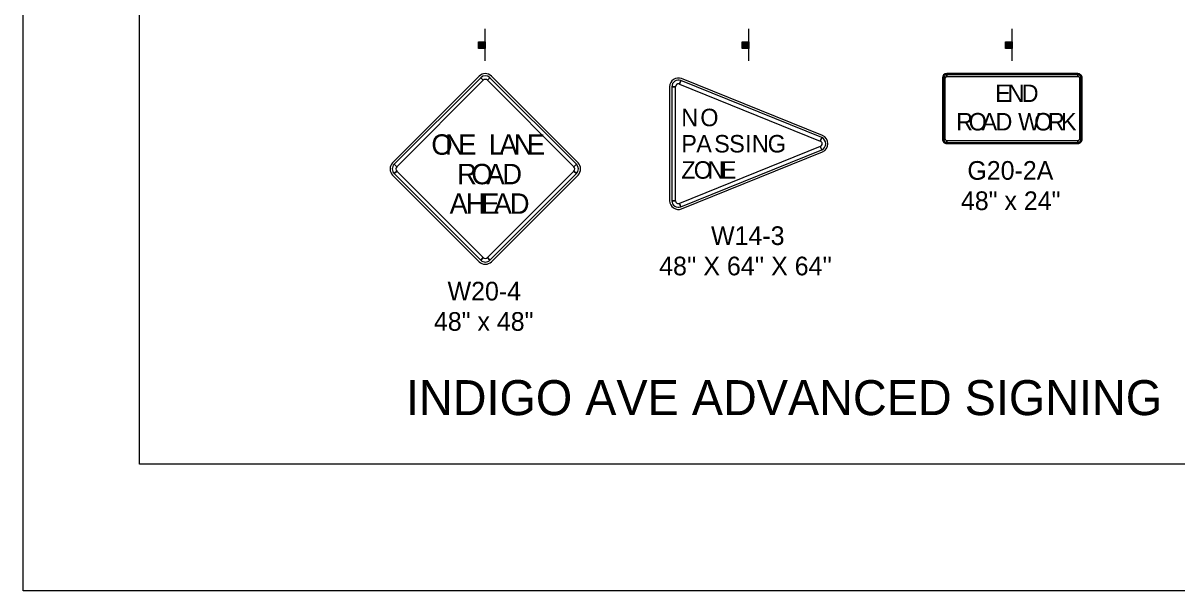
# Model space of a CAD drawing. Extents: x -2134934 to -2122394, y -2139046 to -2137036.
# Drawn here: x -2125529 to -2124540, y -2139046 to -2138559 of the extents above; entities that cross this region are included whole.
import ezdxf

# ---------------------------------------------------------------- set-up
doc = ezdxf.new("R2010")
doc.units = 0
for name, color, linetype in [('Barrier', 7, 'Continuous'), ('BridgeSuperStructureExisting', 7, 'Continuous'), ('Default', 7, 'Continuous')]:
    doc.layers.add(name, color=color, linetype=linetype)

msp = doc.modelspace()

# ---------------------------------------------------------------- linework, layer by layer
at = {"layer": 'Barrier'}
for p, q in [((-2125138.25, -2138604.6), (-2125212.49, -2138678.85)), ((-2125136.92, -2138605.93), (-2125134.71, -2138608.14)), ((-2125131.18, -2138608.14), (-2125128.97, -2138605.93)), ((-2125053.4, -2138678.85), (-2125127.64, -2138604.6)), ((-2124966.38, -2138611.33), (-2124965.21, -2138608.43)), ((-2124843.68, -2138655.57), (-2124964.51, -2138606.7)), ((-2124740.87, -2138606.15), (-2124740.87, -2138658.65)), ((-2124739.93, -2138606.15), (-2124738.37, -2138606.15)), ((-2124624.62, -2138602.4), (-2124737.12, -2138602.4)), ((-2124737.12, -2138604.9), (-2124737.12, -2138603.34)), ((-2124624.62, -2138603.34), (-2124624.62, -2138604.9)), ((-2124623.37, -2138606.15), (-2124621.81, -2138606.15)), ((-2124620.87, -2138658.65), (-2124620.87, -2138606.15)), ((-2124974.82, -2138613.65), (-2124974.82, -2138711.4)), ((-2124972.95, -2138613.65), (-2124969.82, -2138613.65)), ((-2124844.39, -2138657.31), (-2124845.56, -2138660.21)), ((-2124738.37, -2138658.65), (-2124739.93, -2138658.65)), ((-2124737.12, -2138661.47), (-2124737.12, -2138659.9)), ((-2124624.62, -2138659.9), (-2124624.62, -2138661.47)), ((-2124621.81, -2138658.65), (-2124623.37, -2138658.65)), ((-2124964.51, -2138718.35), (-2124843.68, -2138669.48)), ((-2124845.56, -2138664.84), (-2124844.39, -2138667.74)), ((-2124737.12, -2138662.4), (-2124624.62, -2138662.4)), ((-2125212.49, -2138689.45), (-2125138.25, -2138763.7)), ((-2125208.96, -2138682.38), (-2125211.17, -2138680.17)), ((-2125211.17, -2138688.13), (-2125208.96, -2138685.92)), ((-2125127.64, -2138763.7), (-2125053.4, -2138689.45)), ((-2125054.72, -2138680.17), (-2125056.93, -2138682.38)), ((-2125056.93, -2138685.92), (-2125054.72, -2138688.13)), ((-2124969.82, -2138711.4), (-2124972.95, -2138711.4)), ((-2124965.21, -2138716.61), (-2124966.38, -2138713.72)), ((-2125134.71, -2138760.16), (-2125136.92, -2138762.37)), ((-2125128.97, -2138762.37), (-2125131.18, -2138760.16))]:
    msp.add_line(p, q, dxfattribs=at)
for points in [[(-2125429.46, -2138086.59), (-2124308.22, -2138086.59), (-2124308.22, -2138937.23), (-2125429.46, -2138937.23)], [(-2125136.92, -2138605.93), (-2125211.17, -2138680.17), (-2125208.96, -2138682.38), (-2125134.71, -2138608.14), (-2125136.92, -2138605.93)], [(-2125054.72, -2138680.17), (-2125128.97, -2138605.93), (-2125131.18, -2138608.14), (-2125056.93, -2138682.38), (-2125054.72, -2138680.17)], [(-2124844.39, -2138657.31), (-2124965.21, -2138608.43), (-2124966.38, -2138611.33), (-2124845.56, -2138660.21), (-2124844.39, -2138657.31)], [(-2124739.93, -2138606.15), (-2124739.93, -2138658.65), (-2124738.37, -2138658.65), (-2124738.37, -2138606.15), (-2124739.93, -2138606.15)], [(-2124624.62, -2138603.34), (-2124737.12, -2138603.34), (-2124737.12, -2138604.9), (-2124624.62, -2138604.9), (-2124624.62, -2138603.34)], [(-2124621.81, -2138658.65), (-2124621.81, -2138606.15), (-2124623.37, -2138606.15), (-2124623.37, -2138658.65), (-2124621.81, -2138658.65)], [(-2124972.95, -2138613.65), (-2124972.95, -2138711.4), (-2124969.82, -2138711.4), (-2124969.82, -2138613.65), (-2124972.95, -2138613.65)], [(-2124737.12, -2138661.47), (-2124624.62, -2138661.47), (-2124624.62, -2138659.9), (-2124737.12, -2138659.9), (-2124737.12, -2138661.47)], [(-2124965.21, -2138716.61), (-2124844.39, -2138667.74), (-2124845.56, -2138664.84), (-2124966.38, -2138713.72), (-2124965.21, -2138716.61)], [(-2125211.17, -2138688.13), (-2125136.92, -2138762.37), (-2125134.71, -2138760.16), (-2125208.96, -2138685.92), (-2125211.17, -2138688.13)], [(-2125128.97, -2138762.37), (-2125054.72, -2138688.13), (-2125056.93, -2138685.92), (-2125131.18, -2138760.16), (-2125128.97, -2138762.37)]]:
    msp.add_lwpolyline(points, close=True, dxfattribs=at)
for centre, radius, start, end in [((-2125132.94, -2138609.9), 7.5, 44.99999, 134.99974), ((-2125132.94, -2138609.9), 5.62, 44.99999, 134.99974), ((-2125132.94, -2138609.9), 2.5, 44.99999, 134.99974), ((-2124967.32, -2138613.65), 7.5, 67.97571, 179.99985), ((-2124967.32, -2138613.65), 5.62, 67.97571, 179.99985), ((-2124737.12, -2138606.15), 3.75, 90.00021, 179.99985), ((-2124737.12, -2138606.15), 2.81, 90.00021, 179.99985), ((-2124737.12, -2138606.15), 1.25, 90.00021, 179.99985), ((-2124624.62, -2138606.15), 3.75, 0, 90.00021), ((-2124624.62, -2138606.15), 2.81, 0, 90.00021), ((-2124624.62, -2138606.15), 1.25, 0, 90.00021), ((-2124967.32, -2138613.65), 2.5, 67.97571, 179.99985), ((-2124846.5, -2138662.52), 2.5, 292.02456, 67.97541), ((-2124846.5, -2138662.52), 5.62, 292.02456, 67.97541), ((-2124846.5, -2138662.52), 7.5, 292.02456, 67.97598), ((-2124737.12, -2138658.65), 3.75, 179.99985, 270.00006), ((-2124737.12, -2138658.65), 2.81, 179.99985, 270.00006), ((-2124737.12, -2138658.65), 1.25, 179.99985, 270.00006), ((-2124624.62, -2138658.65), 3.75, 270.00006, 0.00027), ((-2124624.62, -2138658.65), 2.81, 270.00006, 0.00027), ((-2124624.62, -2138658.65), 1.25, 270.00006, 0.00027), ((-2125207.19, -2138684.15), 7.5, 134.99974, 224.99995), ((-2125058.7, -2138684.15), 7.5, 315.00016, 44.9998), ((-2125207.19, -2138684.15), 5.62, 134.99974, 224.99995), ((-2125207.19, -2138684.15), 2.5, 134.99974, 224.99995), ((-2125058.7, -2138684.15), 2.5, 315.00016, 44.9998), ((-2125058.7, -2138684.15), 5.62, 315.00016, 44.9998), ((-2124967.32, -2138711.4), 7.5, 179.99985, 292.02456), ((-2124967.32, -2138711.4), 5.62, 179.99985, 292.02456), ((-2124967.32, -2138711.4), 2.5, 179.99985, 292.02456), ((-2125132.94, -2138758.4), 7.5, 224.99995, 315.00016), ((-2125132.94, -2138758.4), 5.62, 224.99995, 315.00016), ((-2125132.94, -2138758.4), 2.5, 224.99995, 315.00016)]:
    msp.add_arc(centre, radius, start, end, dxfattribs=at)
at = {"layer": 'BridgeSuperStructureExisting'}
for p, q in [((-2125132.94, -2138591.58), (-2125132.94, -2138564.08)), ((-2124906.91, -2138591.58), (-2124906.91, -2138564.08)), ((-2124680.87, -2138591.58), (-2124680.87, -2138564.08)), ((-2125138.27, -2138580.72), (-2125138.27, -2138575.13)), ((-2125137.95, -2138575.13), (-2125137.95, -2138580.72)), ((-2125137.73, -2138580.72), (-2125137.73, -2138575.13)), ((-2125137.41, -2138575.13), (-2125137.41, -2138580.72)), ((-2125137.18, -2138580.72), (-2125137.2, -2138575.13)), ((-2125136.77, -2138575.13), (-2125136.75, -2138580.72)), ((-2125136.55, -2138580.72), (-2125136.55, -2138575.13)), ((-2125136.11, -2138575.13), (-2125136.11, -2138580.72)), ((-2125135.74, -2138580.72), (-2125135.74, -2138575.13)), ((-2125135.42, -2138575.13), (-2125135.4, -2138580.72)), ((-2125135.2, -2138580.72), (-2125135.2, -2138575.13)), ((-2125134.93, -2138575.13), (-2125134.93, -2138580.72)), ((-2125134.6, -2138580.72), (-2125134.6, -2138575.13)), ((-2125134.39, -2138575.13), (-2125134.39, -2138580.72)), ((-2125134.16, -2138580.72), (-2125134.16, -2138575.13)), ((-2125133.9, -2138575.13), (-2125133.9, -2138580.72)), ((-2125133.64, -2138580.72), (-2125133.64, -2138575.13)), ((-2125133.36, -2138575.13), (-2125133.36, -2138580.72)), ((-2124912.23, -2138580.72), (-2124912.23, -2138575.13)), ((-2124911.92, -2138575.13), (-2124911.92, -2138580.72)), ((-2124911.69, -2138580.72), (-2124911.69, -2138575.13)), ((-2124911.37, -2138575.13), (-2124911.37, -2138580.72)), ((-2124911.15, -2138580.72), (-2124911.17, -2138575.13)), ((-2124910.73, -2138575.13), (-2124910.72, -2138580.72)), ((-2124910.51, -2138580.72), (-2124910.51, -2138575.13)), ((-2124910.08, -2138575.13), (-2124910.08, -2138580.72)), ((-2124909.7, -2138580.72), (-2124909.7, -2138575.13)), ((-2124909.38, -2138575.13), (-2124909.37, -2138580.72)), ((-2124909.16, -2138580.72), (-2124909.16, -2138575.13)), ((-2124908.9, -2138575.13), (-2124908.9, -2138580.72)), ((-2124908.56, -2138580.72), (-2124908.56, -2138575.13)), ((-2124908.35, -2138575.13), (-2124908.35, -2138580.72)), ((-2124908.13, -2138580.72), (-2124908.13, -2138575.13)), ((-2124907.87, -2138575.13), (-2124907.87, -2138580.72)), ((-2124907.6, -2138580.72), (-2124907.6, -2138575.13)), ((-2124907.32, -2138575.13), (-2124907.32, -2138580.72)), ((-2124686.2, -2138580.72), (-2124686.2, -2138575.13)), ((-2124685.88, -2138575.13), (-2124685.88, -2138580.72)), ((-2124685.65, -2138580.72), (-2124685.65, -2138575.13)), ((-2124685.34, -2138575.13), (-2124685.34, -2138580.72)), ((-2124685.11, -2138580.72), (-2124685.13, -2138575.13)), ((-2124684.7, -2138575.13), (-2124684.68, -2138580.72)), ((-2124684.47, -2138580.72), (-2124684.47, -2138575.13)), ((-2124684.04, -2138575.13), (-2124684.04, -2138580.72)), ((-2124683.67, -2138580.72), (-2124683.67, -2138575.13)), ((-2124683.35, -2138575.13), (-2124683.33, -2138580.72)), ((-2124683.12, -2138580.72), (-2124683.12, -2138575.13)), ((-2124682.86, -2138575.13), (-2124682.86, -2138580.72)), ((-2124682.52, -2138580.72), (-2124682.52, -2138575.13)), ((-2124682.32, -2138575.13), (-2124682.32, -2138580.72)), ((-2124682.09, -2138580.72), (-2124682.09, -2138575.13)), ((-2124681.83, -2138575.13), (-2124681.83, -2138580.72)), ((-2124681.57, -2138580.72), (-2124681.57, -2138575.13)), ((-2124681.29, -2138575.13), (-2124681.29, -2138580.72))]:
    msp.add_line(p, q, dxfattribs=at)
for points in [[(-2125133.04, -2138575.13), (-2125133.04, -2138580.76), (-2125138.66, -2138580.76), (-2125138.66, -2138575.13)], [(-2124907, -2138575.13), (-2124907, -2138580.76), (-2124912.63, -2138580.76), (-2124912.63, -2138575.13)], [(-2124680.97, -2138575.13), (-2124680.97, -2138580.76), (-2124686.59, -2138580.76), (-2124686.59, -2138575.13)]]:
    msp.add_lwpolyline(points, close=True, dxfattribs=at)
at = {"layer": 'Default'}
msp.add_lwpolyline([(-2125529.46, -2137035.95), (-2122394.47, -2137035.95), (-2122394.47, -2139045.94), (-2125529.46, -2139045.94)], close=True, dxfattribs=at)

# ---------------------------------------------------------------- texts
at = {"layer": 'Barrier'}
for s, height, p in [('E', 15, (-2124695.54, -2138626.78)), ('N', 15, (-2124684.93, -2138626.78)), ('D', 15, (-2124672.84, -2138626.78)), ('N', 15, (-2124964.85, -2138647.52)), ('O', 15, (-2124948.51, -2138647.52)), ('R', 15, (-2124729.01, -2138651.15)), ('O', 15, (-2124718.33, -2138651.15)), ('A', 15, (-2124707.17, -2138651.15)), ('D', 15, (-2124695.31, -2138651.15)), ('W', 15, (-2124675.86, -2138651.15)), ('O', 15, (-2124662.13, -2138651.15)), ('R', 15, (-2124650.36, -2138651.15)), ('K', 15, (-2124639.06, -2138651.15)), ('O', 17.5, (-2125179.23, -2138671.96)), ('N', 17.5, (-2125167.45, -2138671.96)), ('E', 17.5, (-2125156.23, -2138671.96)), ('L', 17.5, (-2125129.98, -2138671.96)), ('A', 17.5, (-2125120.78, -2138671.96)), ('N', 17.5, (-2125108.51, -2138671.96)), ('E', 17.5, (-2125097.28, -2138671.96)), ('P', 15, (-2124964.85, -2138670.02)), ('A', 15, (-2124951.96, -2138670.02)), ('S', 15, (-2124936.61, -2138670.02)), ('S', 15, (-2124923.72, -2138670.02)), ('I', 15, (-2124910.12, -2138670.02)), ('N', 15, (-2124904.26, -2138670.02)), ('G', 15, (-2124890.67, -2138670.02)), ('R', 17.5, (-2125157.12, -2138697.27)), ('O', 17.5, (-2125144.83, -2138697.27)), ('A', 17.5, (-2125131.99, -2138697.27)), ('D', 17.5, (-2125118.34, -2138697.27)), ('Z', 15, (-2124964.85, -2138692.52)), ('O', 15, (-2124954.12, -2138692.52)), ('N', 15, (-2124942.28, -2138692.52)), ('E', 15, (-2124930.92, -2138692.52)), ('G20-2A', 16, (-2124719.4, -2138693.4)), ('A', 17.5, (-2125163.56, -2138722.59)), ('H', 17.5, (-2125149.69, -2138722.59)), ('E', 17.5, (-2125136.48, -2138722.59)), ('A', 17.5, (-2125125.76, -2138722.59)), ('D', 17.5, (-2125111.9, -2138722.59)), ('48" x 24"', 16, (-2124724.94, -2138719.4)), ('W14-3', 16, (-2124939.31, -2138749.35)), ("48'' X 64'' X 64''", 16, (-2124983.8, -2138775.35)), ('W20-4', 16, (-2125165.31, -2138796.9)), ('48" x 48"', 16, (-2125177.01, -2138822.9)), ('INDIGO AVE ADVANCED SIGNING', 30, (-2125201.01, -2138895.23))]:
    msp.add_text(s, height=height, dxfattribs=at).set_placement(p)

doc.saveas('drawing.dxf')
